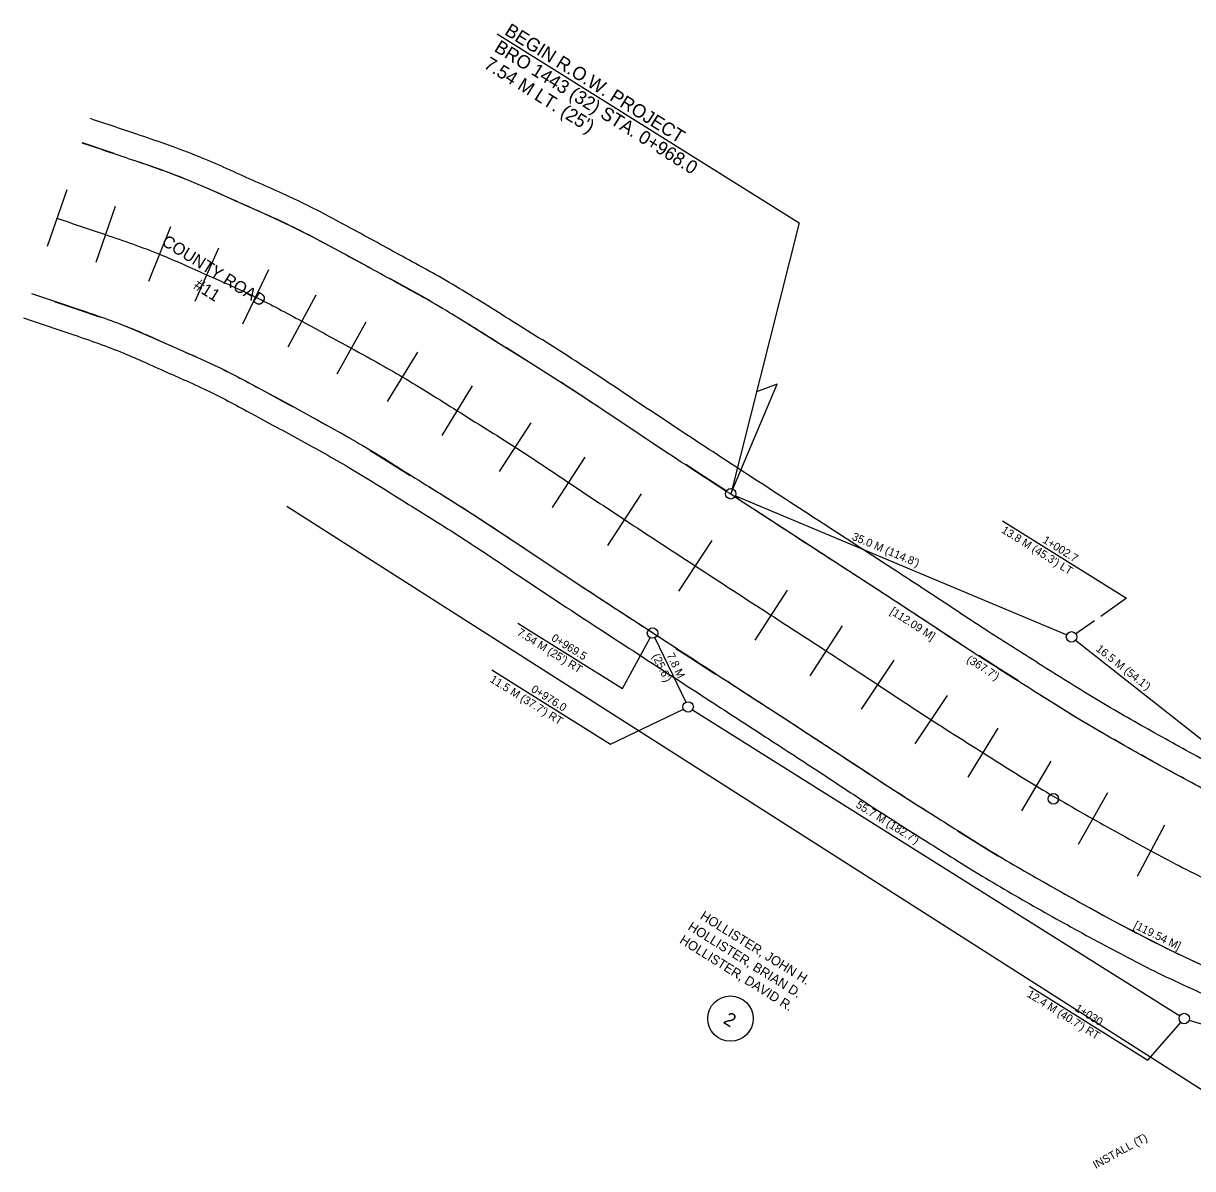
# Model space of a CAD drawing. Extents: x 435838 to 436160, y 121991 to 122158.
# Drawn here: x 435837.9 to 435949.2, y 122048.8 to 122157.8 of the extents above; entities that cross this region are included whole.
import ezdxf

# ---------------------------------------------------------------- set-up
doc = ezdxf.new("R2010")
doc.units = 0
for name, color, linetype in [('Level 1', 7, 'Continuous'), ('Level 10', 7, 'Continuous'), ('Level 12', 7, 'Continuous'), ('Level 2', 7, 'Continuous'), ('Level 3', 7, 'Continuous'), ('Level 4', 7, 'Continuous'), ('Level 5', 7, 'Continuous'), ('Level 7', 7, 'Continuous')]:
    doc.layers.add(name, color=color, linetype=linetype)

msp = doc.modelspace()

# ---------------------------------------------------------------- linework, layer by layer
at = {"layer": 'Level 1'}
for points in [[(435846.563, 122145.401), (435845.876, 122145.632), (435843.528, 122146.423)], [(435871.001, 122134.447), (435870.367, 122134.794), (435867.955, 122136.103), (435865.648, 122137.342), (435863.313, 122138.529), (435860.874, 122139.659), (435858.418, 122140.751), (435856.048, 122141.81), (435853.661, 122142.832), (435850.952, 122143.862), (435848.738, 122144.625)], [(435876.683, 122131.34), (435875.319, 122132.121), (435872.792, 122133.509), (435872.756, 122133.529)], [(435840.878, 122131.316), (435840.957, 122131.29), (435843.223, 122130.526), (435845.134, 122129.868)], [(435899.266, 122116.872), (435896.611, 122118.633), (435893.958, 122120.401), (435891.377, 122122.113), (435888.788, 122123.812), (435885.99, 122125.586), (435883.176, 122127.335), (435880.498, 122129.009), (435878.654, 122130.135)], [(435847.003, 122129.216), (435848.061, 122128.814), (435850.176, 122127.908), (435852.276, 122126.969), (435854.494, 122125.983), (435856.697, 122124.963), (435858.786, 122123.902), (435860.849, 122122.793), (435863.163, 122121.536), (435865.472, 122120.272), (435867.819, 122118.983), (435868.944, 122118.339)], [(435870.914, 122117.137), (435872.659, 122116.071), (435874.737, 122114.772)], [(435904.806, 122113.296), (435902.635, 122114.711), (435900.944, 122115.819)], [(435876.439, 122113.757), (435877.918, 122112.837), (435880.622, 122111.124), (435883.128, 122109.48), (435885.626, 122107.823), (435888.293, 122106.045), (435890.964, 122104.273), (435894.342, 122102.061), (435897.388, 122100.076)], [(435905.983, 122112.528), (435905.643, 122112.75)], [(435927.156, 122098.681), (435925.862, 122099.532), (435923.344, 122101.19), (435920.878, 122102.803), (435918.41, 122104.413), (435915.784, 122106.114), (435913.158, 122107.815), (435909.561, 122110.153), (435907.451, 122111.526)], [(435898.224, 122099.532), (435898.564, 122099.31)], [(435900.016, 122098.319), (435901.312, 122097.476), (435903.785, 122095.868)], [(435932.626, 122095.216), (435930.825, 122096.353), (435928.835, 122097.63)], [(435905.22, 122094.98), (435904.942, 122095.161), (435907.562, 122093.463), (435910.182, 122091.765), (435912.628, 122090.17), (435915.072, 122088.572), (435917.628, 122086.889), (435920.186, 122085.207), (435922.686, 122083.604), (435924.885, 122082.216)], [(435955.996, 122082.096), (435953.937, 122083.053), (435951.329, 122084.359), (435948.751, 122085.721), (435946.066, 122087.186), (435943.396, 122088.676), (435940.783, 122090.164), (435938.195, 122091.695), (435935.711, 122093.23), (435934.56, 122093.954)], [(435926.82, 122080.954), (435927.78, 122080.35), (435930.395, 122078.732), (435930.642, 122078.586)], [(435932.366, 122077.611), (435933.176, 122077.132), (435935.964, 122075.546), (435938.801, 122073.962), (435941.653, 122072.405), (435944.501, 122070.899), (435947.383, 122069.457), (435950.501, 122068.007), (435953.653, 122066.632), (435954.155, 122066.422)]]:
    msp.add_lwpolyline(points, dxfattribs=at)
for points in [[(435994.853, 122072.818), (435994.799, 122072.826), (435987.758, 122074.037), (435980.829, 122075.611), (435973.165, 122077.931), (435966.495, 122080.333), (435960.581, 122082.753), (435955.004, 122085.266), (435949.907, 122087.888), (435944.606, 122090.814), (435939.461, 122093.8), (435934.548, 122096.864), (435929.717, 122099.937), (435924.69, 122103.244), (435919.749, 122106.472), (435914.495, 122109.875), (435907.307, 122114.552), (435900.62, 122118.921), (435895.314, 122122.449), (435890.117, 122125.878), (435884.475, 122129.419), (435879.049, 122132.772), (435873.963, 122135.625), (435869.112, 122138.27), (435864.391, 122140.737), (435859.418, 122142.994), (435854.572, 122145.114), (435849.023, 122147.125), (435844.3, 122148.715)], [(435837.918, 122129.761), (435842.425, 122128.243), (435847.15, 122126.532), (435851.276, 122124.726), (435855.619, 122122.755), (435859.692, 122120.626), (435864.283, 122118.123), (435868.895, 122115.536), (435873.901, 122112.443), (435879.293, 122109.058), (435884.27, 122105.775), (435889.612, 122102.223), (435896.383, 122097.798), (435903.605, 122093.101), (435908.843, 122089.706), (435913.726, 122086.518), (435918.851, 122083.145), (435923.888, 122079.94), (435929.149, 122076.66), (435934.754, 122073.408), (435940.497, 122070.238), (435946.316, 122067.244), (435952.683, 122064.375), (435959.317, 122061.661), (435966.875, 122058.939), (435975.711, 122056.265), (435983.844, 122054.417), (435991.761, 122053.054), (435993.982, 122052.72)]]:
    msp.add_spline(points, degree=3, dxfattribs=at)
at = {"layer": 'Level 10'}
for p, q in [((435883.007, 122156.78), (435911.754, 122138.817)), ((435911.754, 122138.817), (435905.226, 122113.025)), ((435905.226, 122113.025), (435909.649, 122123.462)), ((435909.649, 122123.462), (435907.685, 122122.74))]:
    msp.add_line(p, q, dxfattribs=at)
at = {"layer": 'Level 12'}
for p, q in [((435842.047, 122141.94), (435840.171, 122136.536)), ((435846.648, 122140.342), (435844.8, 122135.026)), ((435851.906, 122138.419), (435849.816, 122133.227)), ((435856.47, 122136.404), (435854.224, 122131.315)), ((435861.254, 122134.337), (435858.755, 122129.155)), ((435865.735, 122131.922), (435863.068, 122126.974)), ((435870.516, 122129.346), (435867.73, 122124.402)), ((435875.415, 122126.499), (435872.528, 122121.809)), ((435880.632, 122123.289), (435877.743, 122118.572)), ((435886.219, 122119.789), (435883.19, 122115.146)), ((435891.35, 122116.511), (435888.234, 122111.712)), ((435896.717, 122113.026), (435893.515, 122108.117)), ((435903.428, 122108.575), (435900.262, 122103.774)), ((435910.592, 122103.863), (435907.507, 122099.112)), ((435915.836, 122100.458), (435912.756, 122095.72)), ((435920.763, 122097.211), (435917.652, 122092.55)), ((435925.807, 122093.844), (435922.761, 122089.237)), ((435930.654, 122090.727), (435927.782, 122086.077)), ((435935.699, 122087.598), (435932.91, 122082.862)), ((435941.067, 122084.571), (435938.292, 122079.651)), ((435946.515, 122081.492), (435943.889, 122076.633))]:
    msp.add_line(p, q, dxfattribs=at)
msp.add_spline([(435841.109, 122139.238), (435845.724, 122137.684), (435850.861, 122135.823), (435855.347, 122133.86), (435860.005, 122131.746), (435864.402, 122129.448), (435869.123, 122126.874), (435873.972, 122124.154), (435879.188, 122120.931), (435884.705, 122117.468), (435889.792, 122114.112), (435895.116, 122110.572), (435901.845, 122106.175), (435909.05, 122101.488), (435914.296, 122098.089), (435919.208, 122094.881), (435924.284, 122091.541), (435929.218, 122088.402), (435934.305, 122085.23), (435939.68, 122082.111), (435945.202, 122079.063), (435950.66, 122076.255), (435956.632, 122073.564), (435962.906, 122070.997), (435970.02, 122068.435), (435978.27, 122065.938), (435985.801, 122064.227), (435993.28, 122062.94), (435998.72, 122062.204), (436004.22, 122061.671)], degree=3, dxfattribs=at)
at = {"layer": 'Level 2'}
for p, q in [((435905.687, 122112.832), (435937.195, 122099.608)), ((435954.334, 122053.582), (435862.989, 122111.831)), ((435898.005, 122099.326), (435900.953, 122093.198)), ((435938.049, 122099.106), (435950.239, 122089.504)), ((435901.593, 122092.482), (435947.96, 122063.371)), ((435948.86, 122062.957), (435984.769, 122051.79))]:
    msp.add_line(p, q, dxfattribs=at)
for points in [[(436004.948, 122069.18), (435999.59, 122069.699), (435994.426, 122070.398), (435987.277, 122071.628), (435980.201, 122073.235), (435972.392, 122075.599), (435965.614, 122078.04), (435959.611, 122080.496), (435953.937, 122083.053), (435948.751, 122085.721), (435943.396, 122088.676), (435938.195, 122091.695), (435933.239, 122094.785), (435928.382, 122097.875), (435923.344, 122101.19), (435918.41, 122104.413), (435913.158, 122107.815), (435905.965, 122112.494), (435899.268, 122116.871), (435893.958, 122120.401), (435888.788, 122123.812), (435883.176, 122127.335), (435877.802, 122130.655), (435872.774, 122133.476), (435867.955, 122136.103), (435863.313, 122138.529), (435858.418, 122140.751), (435853.661, 122142.832), (435848.213, 122144.806), (435843.516, 122146.387)], [(435838.702, 122132.089), (435843.235, 122130.562), (435848.061, 122128.814), (435852.276, 122126.969), (435856.697, 122124.963), (435860.849, 122122.793), (435865.472, 122120.272), (435870.142, 122117.653), (435875.2, 122114.527), (435880.622, 122111.124), (435885.626, 122107.823), (435890.964, 122104.273), (435897.725, 122099.856), (435904.942, 122095.161), (435910.182, 122091.765), (435915.072, 122088.572), (435920.186, 122085.207), (435925.197, 122082.019), (435930.415, 122078.765), (435935.964, 122075.546), (435941.653, 122072.405), (435947.383, 122069.457), (435953.653, 122066.632), (435960.198, 122063.954), (435967.648, 122061.271), (435976.339, 122058.641), (435984.325, 122056.826), (435992.134, 122055.482), (435997.85, 122054.709), (436003.492, 122054.162)]]:
    msp.add_spline(points, degree=3, dxfattribs=at)
at = {"layer": 'Level 3'}
for centre, radius in [((435905.226, 122113.025), 0.4997), ((435897.788, 122099.776), 0.4997), ((435937.656, 122099.415), 0.4997), ((435901.17, 122092.748), 0.4997), ((435935.931, 122084.006), 0.5), ((435948.383, 122063.105), 0.4997)]:
    msp.add_circle(centre, radius, dxfattribs=at)
at = {"layer": 'Level 5'}
for p, q in [((435931.09, 122110.461), (435942.902, 122103.08)), ((435942.902, 122103.08), (435940.433, 122101.355)), ((435884.962, 122100.727), (435894.92, 122094.504)), ((435939.857, 122100.953), (435938.066, 122099.701)), ((435894.92, 122094.504), (435897.549, 122099.337)), ((435882.495, 122096.267), (435893.802, 122089.201)), ((435893.802, 122089.201), (435900.72, 122092.531)), ((435933.667, 122066.176), (435944.923, 122059.141)), ((435944.923, 122059.141), (435948.054, 122062.729))]:
    msp.add_line(p, q, dxfattribs=at)
msp.add_circle((435905.198728, 122063.097696), 2.16, dxfattribs=at)

# ---------------------------------------------------------------- texts
at = {"layer": 'Level 10'}
for s, p in [('BEGIN R.O.W. PROJECT', (435883.62, 122156.772)), ('BRO 1443 (32) STA. 0+968.0', (435882.629, 122155.186)), ("7.54 M LT. (25') ", (435881.638, 122153.6))]:
    msp.add_text(s, height=1.270002, rotation=327.99989998, dxfattribs=at).set_placement(p)
at = {"layer": 'Level 4'}
for s, p in [('HOLLISTER, JOHN H.', (435902.241, 122072.637)), ('HOLLISTER, BRIAN D.', (435901.075, 122071.61)), ('HOLLISTER, DAVID R.', (435900.286, 122070.348))]:
    msp.add_text(s, height=0.889002, rotation=327.99989998, dxfattribs=at).set_placement(p)
at = {"layer": 'Level 5'}
for s, height, p in [('COUNTY ROAD', 1.142808, (435850.99, 122136.754)), ('#11', 1.142808, (435854.015, 122132.606)), ("13.8 M (45.3') LT", 0.761874, (435930.922, 122109.38)), ('1+002.7', 0.761874, (435934.831, 122108.442)), ("7.54 M (25') RT", 0.761874, (435884.828, 122099.65)), ('0+969.5', 0.761874, (435888.091, 122099.116)), ("11.5 M (37.7') RT", 0.761874, (435882.25, 122095.18)), ('0+976.0', 0.761874, (435886.159, 122094.242)), ("12.4 M (40.7') RT", 0.761874, (435933.353, 122065.241)), ('1+030', 0.761874, (435937.908, 122063.899)), ('2', 1.270002, (435904.426, 122062.726))]:
    msp.add_text(s, height=height, rotation=327.99989998, dxfattribs=at).set_placement(p)
at = {"layer": 'Level 7'}
for s, height, rotation, p in [("35.0 M (114.8')", 0.761862, 337.2320643, (435916.702, 122108.68)), ('[112.09 M]', 0.761874, 327.21502022, (435920.319, 122101.66)), ("(25.6')", 0.761874, 295.69083459, (435897.733, 122097.606)), ('7.8 M', 0.761874, 295.69083459, (435899.112, 122097.684)), ("16.5 M (54.1')", 0.761868, 321.7726785, (435939.913, 122098.148)), ("(367.7')", 0.761874, 327.21502022, (435927.612, 122097.095)), ("55.7 M (182.7')", 0.761868, 328.37780475, (435917.064, 122083.25)), ('[119.54 M]', 0.761862, 333.71208242, (435943.501, 122071.736)), ('INSTALL (T)', 0.761874, 28.95719819, (435939.955, 122048.783))]:
    msp.add_text(s, height=height, rotation=rotation, dxfattribs=at).set_placement(p)

doc.saveas('drawing.dxf')
